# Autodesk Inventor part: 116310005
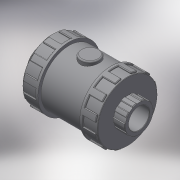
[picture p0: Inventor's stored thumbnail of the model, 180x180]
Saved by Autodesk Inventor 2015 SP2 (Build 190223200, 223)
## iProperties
Created: 2017-11
Part Number: 116310005
Material: Generic
Description: PLASSON AIR RELEASE VALVE THR PVC 1/2"
Document SubType Name: Modeling
Designer: KIM
Density: 1 g/cm^3
Appearance: Default
Author: KIM
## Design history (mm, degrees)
derived "116310 - 116910.ipt"
feature "Solid1::116310 - 116910.ipt"
tag "TaggingFeature1"
body "Solid1"
other parameters: "d0" = 75, "d1" = 18.631, "d2" = 45, "d3" = 15, "d4" = 14.9048, "d5" = 10.5, "d7" = 26.0834, "d8" = 40.5, "d13" = 0.55893, "d23" = 15, "d24" = 43.2, "d25" = 0.37262, "d26" = 0.55893, "d27" = 6.75, "d28" = 3.375, "d29" = 11.25, "d30" = 0, "d35" = 0.55893, "d39" = 22.5, "d45" = 360 deg, "d47" = 0.37262, "d50" = 22.5, "d51" = 13.5, "d53" = 0, "d54" = 0.9, "d55" = 3.7262, "d56" = 1.8631, "d58" = 0, "d59" = 0.55893, "d61" = 360 deg, "G_" = 18.631, "l_" = 15, "H_" = 75, "K_" = 45
